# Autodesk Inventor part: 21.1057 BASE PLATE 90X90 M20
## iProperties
Created: 2007-03
Part Number: 21.1057 BASE PLATE 90X90 M20
Document SubType Name: Modeling
Designer: Andy Moles
Material: Aluminum-6061
Mass: 298.369 g
Surface Area: 231.341 cm^2
Volume: 110.099 cm^3
Density: 2.71 g/cm^3
Author: Andy Moles
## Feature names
1. Extrusion1
2. Fillet1
3. Hole1
4. Hole2
5. Hole3
6. Hole4
7. Fillet2
